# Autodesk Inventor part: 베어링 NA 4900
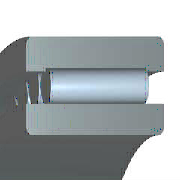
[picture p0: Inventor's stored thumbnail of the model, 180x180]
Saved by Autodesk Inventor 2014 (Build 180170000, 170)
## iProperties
Created: 2009-02
Part Number: 베어링 NA 4900
Material: Steel, Mild
Description: 니들 롤러 베어링 - 경계 치수 및 공차
Document SubType Name: Modeling
Standard: KS B 2029
Designer: KYOUNG IL JANG
Standards Organization: KS
Language: ko-KR
Size Designation: NA 4900 - 10 x 22 x 13
Categories: <MemberInstance><Categories><Category DisplayName="샤프트 부품" InternalName="7f7aeb1f-a693-4053-b835-cee3144e0d98" Mnemonic="SHFT"><Category DisplayName="베어링" Inter
Density: 7.86 g/cm^3
Mass: 23.8214 g
Surface Area: 38.613 cm^2
Volume: 3.03071 cm^3
Appearance: Metal-Steel
Company: 한국ATC센터
IsCustomPart: 0
Author: KYOUNG IL JANG
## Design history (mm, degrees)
sketch "스케치"
  geometry: L1 (1.857, 9)-(11.143, 9); L2 (11.143, 9)-(11.143, 7); L3 (13, 7)-(0, 7); L4 (1.857, 7)-(1.857, 9); L5 (1.857, 8)-(11.143, 8); L6 (6.5, 8)-(6.5, 7); L7 (0, 5)-(13, 5); L8 (0, 11)-(13, 11); L9 (13, 5)-(13, 7); L10 (13, 8.8)-(13, 11); L11 (1.857, 8.8)-(0, 8.8); L12 (11.143, 8.8)-(13, 8.8); L13 (-6, 0)-(36, 0) reference; L14 (0, -1.9)-(0, 14.9) reference
  constraints: 24 end point, 8 point on line, 3 midpoint, 3 parallel, 3 perpendicular, 2 symmetric about line, 1 horizontal, 1 other
  dimensions: "d6" = 10 diameter of L7 L13 (= WD); "d7" = 14 diameter of L3 L13 (= KID1); "d8" = 22 diameter of L8 L13 (= BD); "d9" = 16 diameter of L6.start L13 (= 0.5 x WD + 0.5 x BD); "d10" = 17.6 diameter of L12 L13 (= 0.9 x BD + 0.9 x WD - 0.8 x KID1); "d11" = 18 diameter of L1 L13 (= BD + WD - KID1); "d12" = 1.85714 distance between parallel lines of L14 L4 (= 0.142857 x KB); "d13" = 13 distance between parallel lines of L14 L9 (= KB); "d14" = 11.14286 distance between parallel lines of L14 L2 (= 0.857143 x KB)
revolve "본체" stored, may be unused: angle "d17" = 90 deg
revolve "롤러" stored, may be unused: angle "d18" = 90 deg
pattern_circular "IDS_ARRAYROLLER[SIMPL:T]" dims angle "d2" = 360 deg
body "Solid1"
fillet "모깎기1" dims "d0" = 0.3 (= KRS)
other parameters: "WD" = 10 [user parameter; used in 6 equation terms], "BD" = 22 [user parameter; used in 6 equation terms], "KB" = 13 [user parameter; used in 3 equation terms], "KID1" = 14 [user parameter; used in 4 equation terms], "KRS" = 0.3 [user parameter; used in 1 equation term], "d3" = 0, "d4" = 0, "d5" = 0, "d15" = 0, "d16" = 0, "BC0" = 9150000 [user parameter], "WR" = 5 (= 0.5 x WD) [user parameter], "BBA" = 0 [user parameter], "BC" = 8150000 [user parameter], "BR" = 11 (= 0.5 x BD) [user parameter]
